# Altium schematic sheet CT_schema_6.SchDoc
size 218 x 258 mm
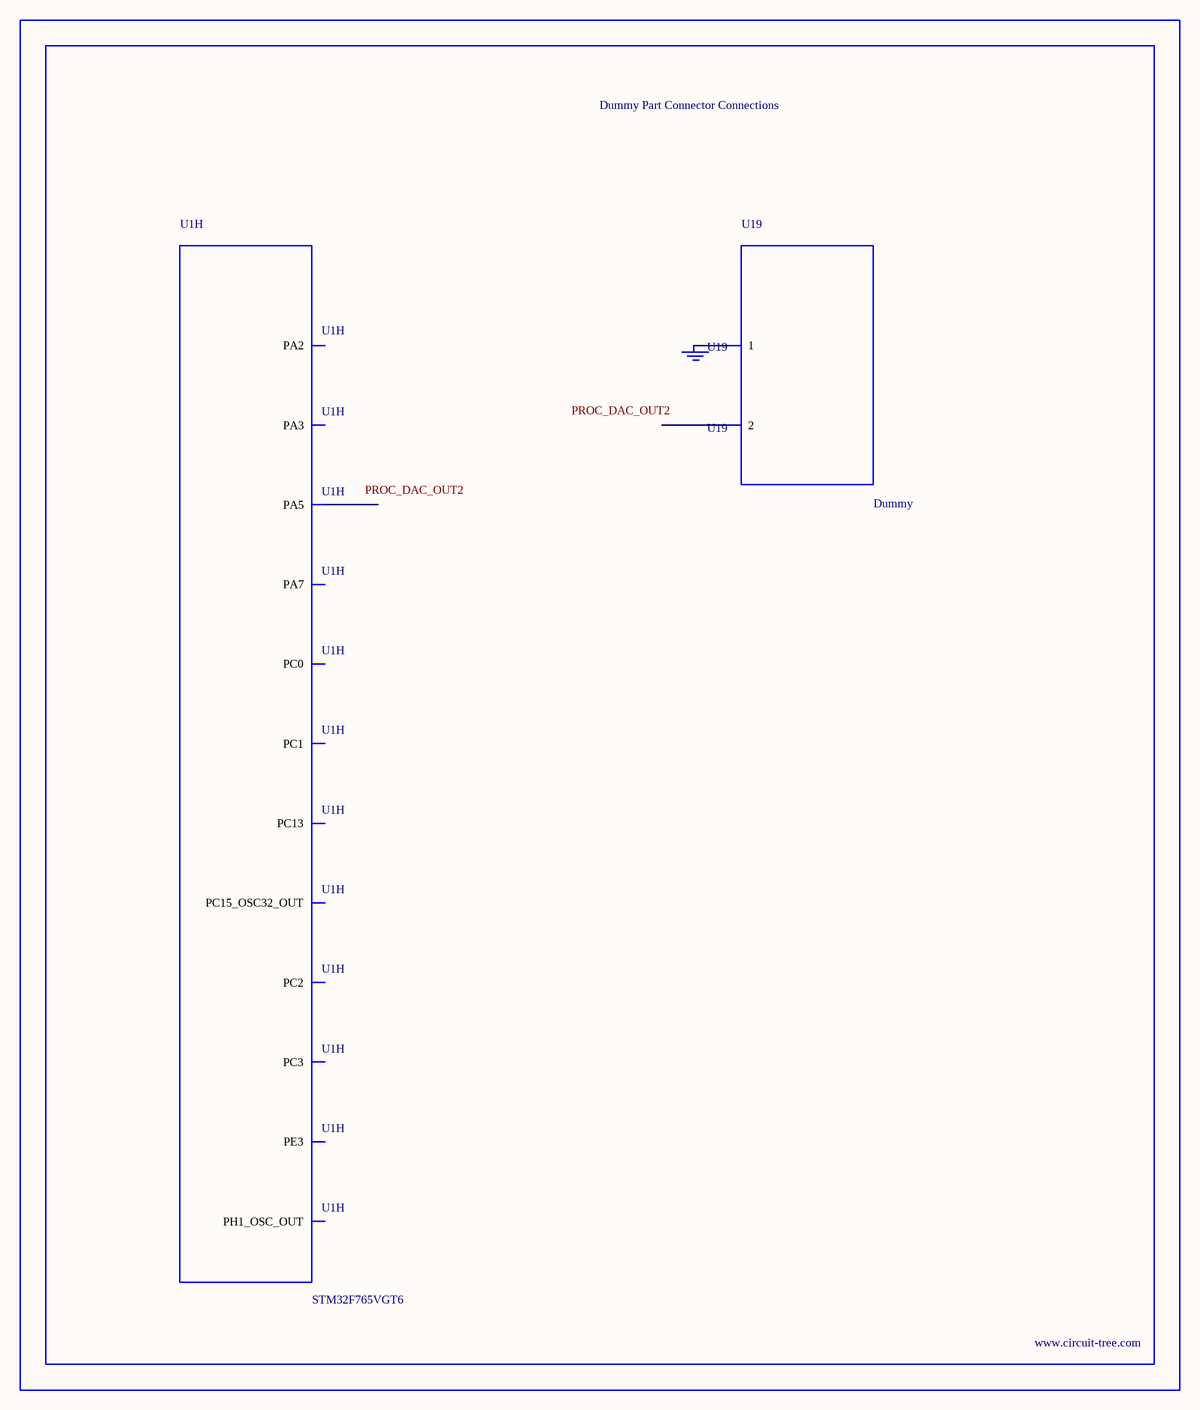
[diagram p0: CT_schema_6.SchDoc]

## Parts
BORDER5  (no value)
GND_INSTANCE_5_0  (no value)
U1  STM32F765VGT6  [LQFP100]  (part H of 8)
U19  Dummy  [DUMMY_PACKAGE_160]

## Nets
NetGND_INSTANCE_5_0_0: GND_INSTANCE_5_0.0(GND) U19.1

Not connected (* = marked no-connect by the designer): U1 2(PE3) 7(PC13) 9(PC15_OSC32_OUT) 13(PH1_OSC_OUT) 15(PC0) 16(PC1) 17(PC2) 18(PC3) 24(PA2) 25(PA3) 29(PA5) 31(PA7); U19 2

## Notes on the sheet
- Labels drawn without touching a wire or pin: PROC_DAC_OUT2

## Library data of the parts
BORDER5 = BORDER_PAGE5
GND_INSTANCE_5_0 = GND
